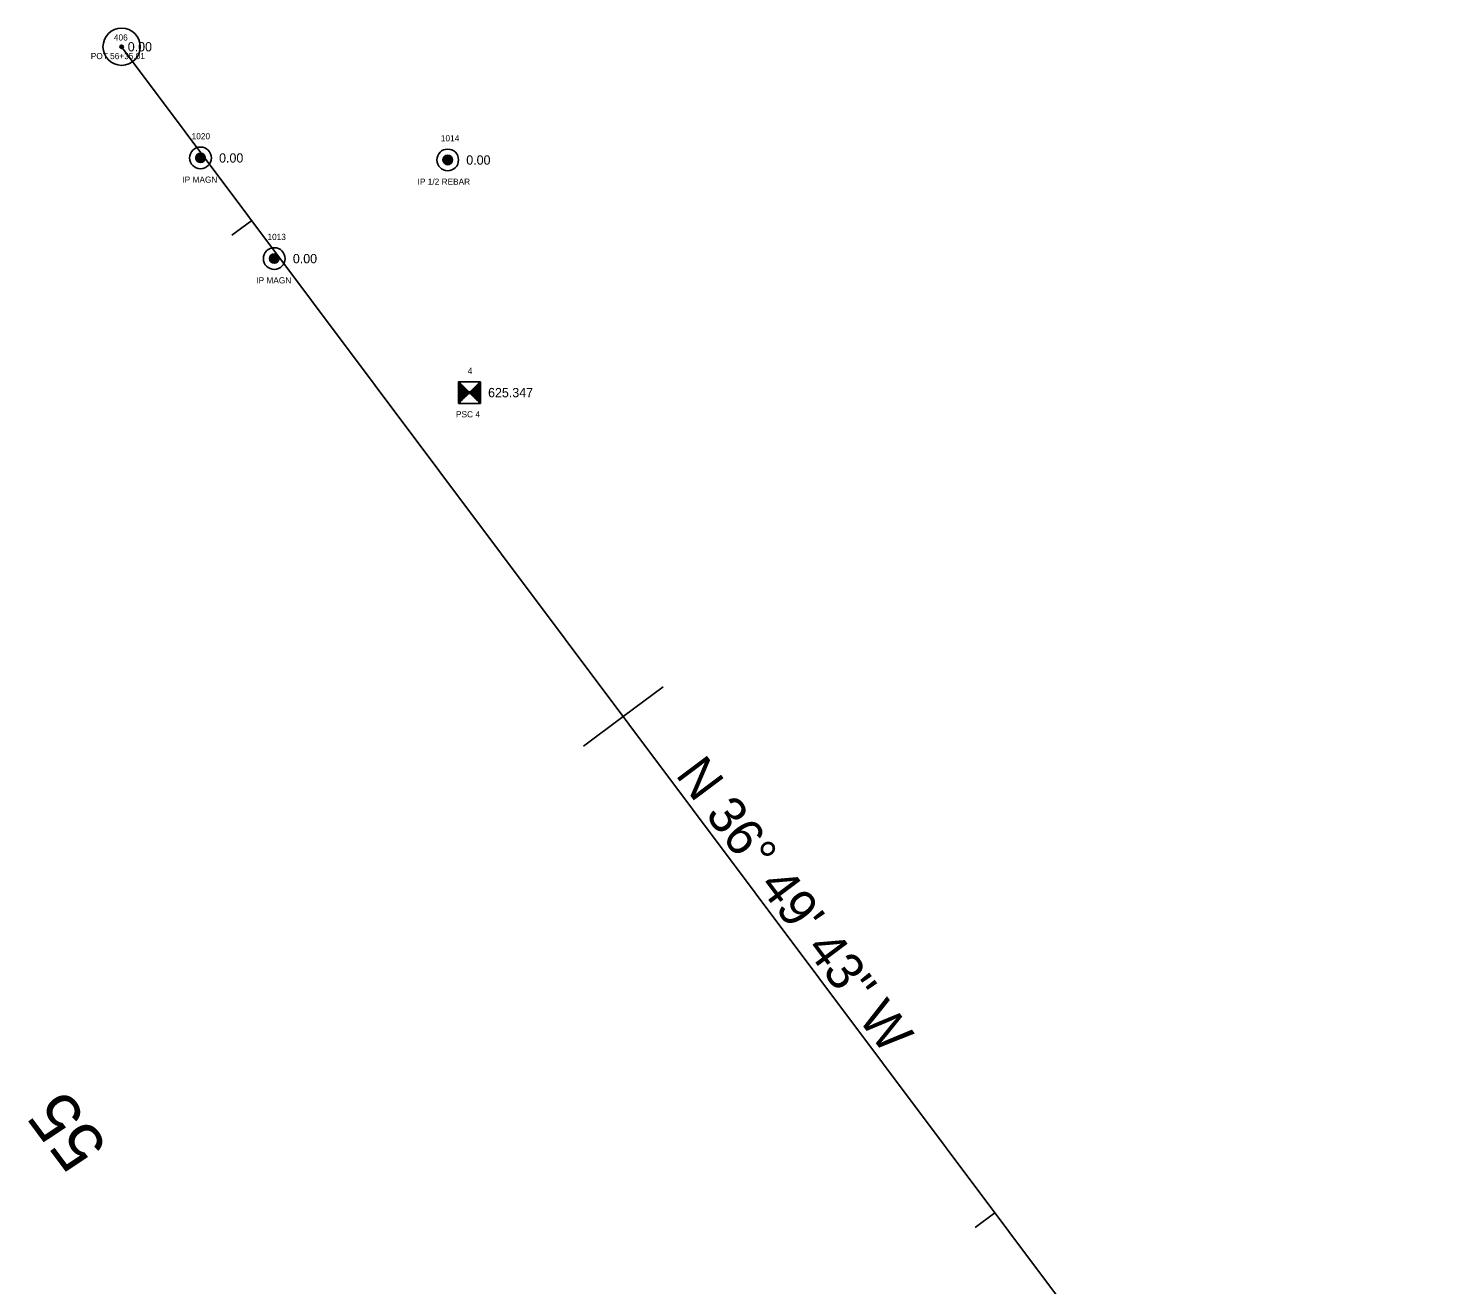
# Model space of a CAD drawing. Extents: x 1538847 to 1546108, y 887169 to 888935.
# Drawn here: x 1539801.6 to 1540028.6, y 887929.8 to 888132.6 of the extents above; entities that cross this region are included whole.
import ezdxf

# ---------------------------------------------------------------- set-up
doc = ezdxf.new("R2010")
doc.units = 0
for name, color, linetype in [('Default', 7, 'Continuous'), ('RD_EX_DV_Prop_txCode', 7, 'Continuous'), ('RD_EX_DV_PropPin', 7, 'Continuous'), ('RD_EX_TX_DV_Prop_ELEV', 7, 'Continuous'), ('RD_HC_Cl', 7, 'Continuous'), ('RD_HC_Data', 7, 'Continuous'), ('RD_HC_Data_Tic', 7, 'Continuous'), ('RD_HC_Survey', 7, 'Continuous'), ('RD_HC_Survey_ELEV', 7, 'Continuous'), ('RD_HC_TX_Sta50', 7, 'Continuous'), ('RD_HC_txCode', 7, 'Continuous'), ('RD_SMD_Locator', 7, 'Continuous')]:
    doc.layers.add(name, color=color, linetype=linetype)

msp = doc.modelspace()

# ---------------------------------------------------------------- linework, layer by layer
at = {"layer": 'Default'}
msp.add_line((1540028.65, 887846.48), (1539816.65, 888129.56), dxfattribs=at)
at = {"layer": 'RD_EX_DV_PropPin'}
for p, q in [((1539828.64, 888111.43), (1539828.64, 888111.82)), ((1539828.68, 888111.32), (1539828.68, 888111.92)), ((1539828.71, 888111.25), (1539828.71, 888111.99)), ((1539828.75, 888111.2), (1539828.75, 888112.05)), ((1539828.78, 888111.15), (1539828.78, 888112.1)), ((1539828.82, 888111.11), (1539828.82, 888112.14)), ((1539828.85, 888111.07), (1539828.85, 888112.17)), ((1539828.89, 888111.04), (1539828.89, 888112.2)), ((1539828.92, 888111.01), (1539828.92, 888112.23)), ((1539828.96, 888110.99), (1539828.96, 888112.26)), ((1539828.99, 888110.97), (1539828.99, 888112.28)), ((1539829.03, 888110.95), (1539829.03, 888112.3)), ((1539829.06, 888110.93), (1539829.06, 888112.32)), ((1539829.1, 888110.92), (1539829.1, 888112.33)), ((1539829.13, 888110.9), (1539829.13, 888112.34)), ((1539829.17, 888110.89), (1539829.17, 888112.35)), ((1539829.2, 888110.88), (1539829.2, 888112.36)), ((1539829.24, 888110.87), (1539829.24, 888112.37)), ((1539829.27, 888110.87), (1539829.27, 888112.38)), ((1539829.31, 888110.86), (1539829.31, 888112.38)), ((1539829.34, 888110.86), (1539829.34, 888112.38)), ((1539829.38, 888110.86), (1539829.38, 888112.38)), ((1539829.41, 888110.86), (1539829.41, 888112.38)), ((1539829.45, 888110.86), (1539829.45, 888112.38)), ((1539829.48, 888110.87), (1539829.48, 888112.38)), ((1539829.52, 888110.87), (1539829.52, 888112.37)), ((1539829.55, 888110.88), (1539829.55, 888112.36)), ((1539829.59, 888110.89), (1539829.59, 888112.35)), ((1539829.62, 888110.9), (1539829.62, 888112.34)), ((1539829.66, 888110.92), (1539829.66, 888112.33)), ((1539829.69, 888110.93), (1539829.69, 888112.32)), ((1539829.73, 888110.95), (1539829.73, 888112.3)), ((1539829.76, 888110.97), (1539829.76, 888112.28)), ((1539829.8, 888110.99), (1539829.8, 888112.26)), ((1539829.83, 888111.01), (1539829.83, 888112.23)), ((1539829.87, 888111.04), (1539829.87, 888112.2)), ((1539829.9, 888111.07), (1539829.9, 888112.17)), ((1539829.94, 888111.11), (1539829.94, 888112.14)), ((1539829.97, 888111.15), (1539829.97, 888112.1)), ((1539830.01, 888111.2), (1539830.01, 888112.05)), ((1539830.04, 888111.25), (1539830.04, 888111.99)), ((1539830.08, 888111.32), (1539830.08, 888111.92)), ((1539830.11, 888111.43), (1539830.11, 888111.82)), ((1539868.52, 888111.09), (1539868.52, 888111.48)), ((1539868.55, 888110.99), (1539868.55, 888111.58)), ((1539868.59, 888110.92), (1539868.59, 888111.66)), ((1539868.62, 888110.86), (1539868.62, 888111.71)), ((1539868.66, 888110.81), (1539868.66, 888111.76)), ((1539868.69, 888110.77), (1539868.69, 888111.8)), ((1539868.73, 888110.74), (1539868.73, 888111.84)), ((1539868.76, 888110.7), (1539868.76, 888111.87)), ((1539868.8, 888110.68), (1539868.8, 888111.9)), ((1539868.83, 888110.65), (1539868.83, 888111.92)), ((1539868.87, 888110.63), (1539868.87, 888111.94)), ((1539868.9, 888110.61), (1539868.9, 888111.96)), ((1539868.94, 888110.59), (1539868.94, 888111.98)), ((1539868.97, 888110.58), (1539868.97, 888111.99)), ((1539869.01, 888110.57), (1539869.01, 888112.01)), ((1539869.04, 888110.55), (1539869.04, 888112.02)), ((1539869.08, 888110.55), (1539869.08, 888112.03)), ((1539869.11, 888110.54), (1539869.11, 888112.03)), ((1539869.15, 888110.53), (1539869.15, 888112.04)), ((1539869.18, 888110.53), (1539869.18, 888112.04)), ((1539869.22, 888110.53), (1539869.22, 888112.05)), ((1539869.25, 888110.52), (1539869.25, 888112.05)), ((1539869.29, 888110.53), (1539869.29, 888112.05)), ((1539869.32, 888110.53), (1539869.32, 888112.04)), ((1539869.36, 888110.53), (1539869.36, 888112.04)), ((1539869.39, 888110.54), (1539869.39, 888112.03)), ((1539869.43, 888110.55), (1539869.43, 888112.03)), ((1539869.46, 888110.55), (1539869.46, 888112.02)), ((1539869.5, 888110.57), (1539869.5, 888112.01)), ((1539869.53, 888110.58), (1539869.53, 888111.99)), ((1539869.57, 888110.59), (1539869.57, 888111.98)), ((1539869.6, 888110.61), (1539869.6, 888111.96)), ((1539869.64, 888110.63), (1539869.64, 888111.94)), ((1539869.67, 888110.65), (1539869.67, 888111.92)), ((1539869.71, 888110.68), (1539869.71, 888111.9)), ((1539869.74, 888110.7), (1539869.74, 888111.87)), ((1539869.78, 888110.74), (1539869.78, 888111.84)), ((1539869.81, 888110.77), (1539869.81, 888111.8)), ((1539869.85, 888110.81), (1539869.85, 888111.76)), ((1539869.88, 888110.86), (1539869.88, 888111.71)), ((1539869.92, 888110.92), (1539869.92, 888111.66)), ((1539869.95, 888110.99), (1539869.95, 888111.58)), ((1539869.99, 888111.09), (1539869.99, 888111.48)), ((1539840.55, 888095.18), (1539840.55, 888095.58)), ((1539840.58, 888095.08), (1539840.58, 888095.68)), ((1539840.62, 888095.01), (1539840.62, 888095.75)), ((1539840.65, 888094.95), (1539840.65, 888095.81)), ((1539840.69, 888094.91), (1539840.69, 888095.85)), ((1539840.72, 888094.87), (1539840.72, 888095.9)), ((1539840.76, 888094.83), (1539840.76, 888095.93)), ((1539840.79, 888094.8), (1539840.79, 888095.96)), ((1539840.83, 888094.77), (1539840.83, 888095.99)), ((1539840.86, 888094.75), (1539840.86, 888096.02)), ((1539840.9, 888094.72), (1539840.9, 888096.04)), ((1539840.93, 888094.7), (1539840.93, 888096.06)), ((1539840.97, 888094.69), (1539840.97, 888096.07)), ((1539841, 888094.67), (1539841, 888096.09)), ((1539841.04, 888094.66), (1539841.04, 888096.1)), ((1539841.07, 888094.65), (1539841.07, 888096.11)), ((1539841.11, 888094.64), (1539841.11, 888096.12)), ((1539841.14, 888094.63), (1539841.14, 888096.13)), ((1539841.18, 888094.63), (1539841.18, 888096.13)), ((1539841.21, 888094.62), (1539841.21, 888096.14)), ((1539841.25, 888094.62), (1539841.25, 888096.14)), ((1539841.28, 888094.62), (1539841.28, 888096.14)), ((1539841.32, 888094.62), (1539841.32, 888096.14)), ((1539841.35, 888094.62), (1539841.35, 888096.14)), ((1539841.39, 888094.63), (1539841.39, 888096.13)), ((1539841.42, 888094.63), (1539841.42, 888096.13)), ((1539841.46, 888094.64), (1539841.46, 888096.12)), ((1539841.49, 888094.65), (1539841.49, 888096.11)), ((1539841.53, 888094.66), (1539841.53, 888096.1)), ((1539841.56, 888094.67), (1539841.56, 888096.09)), ((1539841.6, 888094.69), (1539841.6, 888096.07)), ((1539841.63, 888094.7), (1539841.63, 888096.06)), ((1539841.67, 888094.72), (1539841.67, 888096.04)), ((1539841.7, 888094.75), (1539841.7, 888096.02)), ((1539841.74, 888094.77), (1539841.74, 888095.99)), ((1539841.77, 888094.8), (1539841.77, 888095.96)), ((1539841.81, 888094.83), (1539841.81, 888095.93)), ((1539841.84, 888094.87), (1539841.84, 888095.9)), ((1539841.88, 888094.91), (1539841.88, 888095.85)), ((1539841.91, 888094.95), (1539841.91, 888095.81)), ((1539841.95, 888095.01), (1539841.95, 888095.75)), ((1539841.98, 888095.08), (1539841.98, 888095.68)), ((1539842.02, 888095.18), (1539842.02, 888095.58))]:
    msp.add_line(p, q, dxfattribs=at)
for centre, radius in [((1539829.38, 888111.62), 1.75), ((1539829.38, 888111.62), 0.761), ((1539869.25, 888111.29), 1.75), ((1539869.25, 888111.29), 0.761), ((1539841.28, 888095.38), 1.75), ((1539841.28, 888095.38), 0.761)]:
    msp.add_circle(centre, radius, dxfattribs=at)
at = {"layer": 'RD_HC_Cl'}
msp.add_line((1540028.65, 887846.48), (1539816.65, 888129.56), dxfattribs=at)
at = {"layer": 'RD_HC_Data'}
for radius in [3, 0.282]:
    msp.add_circle((1539816.65, 888129.56), radius, dxfattribs=at)
at = {"layer": 'RD_HC_Data_Tic'}
for p, q in [((1539837.64, 888101.54), (1539834.44, 888099.14)), ((1539897.58, 888021.49), (1539903.99, 888026.29)), ((1539897.58, 888021.49), (1539891.18, 888016.7)), ((1539957.53, 887941.45), (1539954.32, 887939.05))]:
    msp.add_line(p, q, dxfattribs=at)
at = {"layer": 'RD_HC_Survey'}
for p, q in [((1539871.02, 888075.51), (1539874.52, 888072.01)), ((1539874.52, 888075.51), (1539871.02, 888072.01)), ((1539871.04, 888075.48), (1539871.04, 888072.03)), ((1539871.07, 888075.46), (1539871.07, 888072.06)), ((1539871.09, 888075.44), (1539871.09, 888072.08)), ((1539871.12, 888075.41), (1539871.12, 888072.11)), ((1539871.14, 888075.39), (1539871.14, 888072.13)), ((1539871.17, 888075.36), (1539871.17, 888072.16)), ((1539871.19, 888075.34), (1539871.19, 888072.18)), ((1539871.22, 888075.31), (1539871.22, 888072.21)), ((1539871.24, 888075.29), (1539871.24, 888072.23)), ((1539871.27, 888075.26), (1539871.27, 888072.26)), ((1539871.29, 888075.24), (1539871.29, 888072.28)), ((1539871.31, 888075.21), (1539871.31, 888072.31)), ((1539871.34, 888075.19), (1539871.34, 888072.33)), ((1539871.36, 888075.16), (1539871.36, 888072.36)), ((1539871.39, 888075.14), (1539871.39, 888072.38)), ((1539871.41, 888075.11), (1539871.41, 888072.41)), ((1539871.44, 888075.09), (1539871.44, 888072.43)), ((1539871.46, 888075.06), (1539871.46, 888072.45)), ((1539871.49, 888075.04), (1539871.49, 888072.48)), ((1539871.51, 888075.01), (1539871.51, 888072.5)), ((1539871.54, 888074.99), (1539871.54, 888072.53)), ((1539871.56, 888074.97), (1539871.56, 888072.55)), ((1539871.59, 888074.94), (1539871.59, 888072.58)), ((1539871.61, 888074.92), (1539871.61, 888072.6)), ((1539871.64, 888074.89), (1539871.64, 888072.63)), ((1539871.66, 888074.87), (1539871.66, 888072.65)), ((1539871.69, 888074.84), (1539871.69, 888072.68)), ((1539871.71, 888074.82), (1539871.71, 888072.7)), ((1539871.74, 888074.79), (1539871.74, 888072.73)), ((1539871.76, 888074.77), (1539871.76, 888072.75)), ((1539871.79, 888074.74), (1539871.79, 888072.78)), ((1539871.81, 888074.72), (1539871.81, 888072.8)), ((1539873.73, 888074.72), (1539873.73, 888072.8)), ((1539873.75, 888074.74), (1539873.75, 888072.78)), ((1539873.78, 888074.77), (1539873.78, 888072.75)), ((1539873.8, 888074.79), (1539873.8, 888072.73)), ((1539873.82, 888074.82), (1539873.82, 888072.7)), ((1539873.85, 888074.84), (1539873.85, 888072.68)), ((1539873.87, 888074.87), (1539873.87, 888072.65)), ((1539873.9, 888074.89), (1539873.9, 888072.63)), ((1539873.92, 888074.92), (1539873.92, 888072.6)), ((1539873.95, 888074.94), (1539873.95, 888072.58)), ((1539873.97, 888074.97), (1539873.97, 888072.55)), ((1539874, 888074.99), (1539874, 888072.53)), ((1539874.02, 888075.01), (1539874.02, 888072.5)), ((1539874.05, 888075.04), (1539874.05, 888072.48)), ((1539874.07, 888075.06), (1539874.07, 888072.45)), ((1539874.1, 888075.09), (1539874.1, 888072.43)), ((1539874.12, 888075.11), (1539874.12, 888072.41)), ((1539874.15, 888075.14), (1539874.15, 888072.38)), ((1539874.17, 888075.16), (1539874.17, 888072.36)), ((1539874.2, 888075.19), (1539874.2, 888072.33)), ((1539874.22, 888075.21), (1539874.22, 888072.31)), ((1539874.25, 888075.24), (1539874.25, 888072.28)), ((1539874.27, 888075.26), (1539874.27, 888072.26)), ((1539874.3, 888075.29), (1539874.3, 888072.23)), ((1539874.32, 888075.31), (1539874.32, 888072.21)), ((1539874.34, 888075.34), (1539874.34, 888072.18)), ((1539874.37, 888075.36), (1539874.37, 888072.16)), ((1539874.39, 888075.39), (1539874.39, 888072.13)), ((1539874.42, 888075.41), (1539874.42, 888072.11)), ((1539874.44, 888075.44), (1539874.44, 888072.08)), ((1539874.47, 888075.46), (1539874.47, 888072.06)), ((1539874.49, 888075.48), (1539874.49, 888072.03)), ((1539871.83, 888074.69), (1539871.83, 888072.83)), ((1539871.86, 888074.67), (1539871.86, 888072.85)), ((1539871.88, 888074.64), (1539871.88, 888072.88)), ((1539871.91, 888074.62), (1539871.91, 888072.9)), ((1539871.93, 888074.59), (1539871.93, 888072.93)), ((1539871.96, 888074.57), (1539871.96, 888072.95)), ((1539871.98, 888074.54), (1539871.98, 888072.97)), ((1539872.01, 888074.52), (1539872.01, 888073)), ((1539872.03, 888074.49), (1539872.03, 888073.02)), ((1539872.06, 888074.47), (1539872.06, 888073.05)), ((1539872.08, 888074.45), (1539872.08, 888073.07)), ((1539872.11, 888074.42), (1539872.11, 888073.1)), ((1539872.13, 888074.4), (1539872.13, 888073.12)), ((1539872.16, 888074.37), (1539872.16, 888073.15)), ((1539872.18, 888074.35), (1539872.18, 888073.17)), ((1539872.21, 888074.32), (1539872.21, 888073.2)), ((1539872.23, 888074.3), (1539872.23, 888073.22)), ((1539872.26, 888074.27), (1539872.26, 888073.25)), ((1539872.28, 888074.25), (1539872.28, 888073.27)), ((1539872.3, 888074.22), (1539872.3, 888073.3)), ((1539872.33, 888074.2), (1539872.33, 888073.32)), ((1539872.35, 888074.17), (1539872.35, 888073.35)), ((1539872.38, 888074.15), (1539872.38, 888073.37)), ((1539872.4, 888074.12), (1539872.4, 888073.4)), ((1539872.43, 888074.1), (1539872.43, 888073.42)), ((1539872.45, 888074.07), (1539872.45, 888073.44)), ((1539872.48, 888074.05), (1539872.48, 888073.47)), ((1539872.5, 888074.02), (1539872.5, 888073.49)), ((1539872.53, 888074), (1539872.53, 888073.52)), ((1539872.55, 888073.98), (1539872.55, 888073.54)), ((1539872.58, 888073.95), (1539872.58, 888073.57)), ((1539872.6, 888073.93), (1539872.6, 888073.59)), ((1539872.63, 888073.9), (1539872.63, 888073.62)), ((1539872.65, 888073.88), (1539872.65, 888073.64)), ((1539872.68, 888073.85), (1539872.68, 888073.67)), ((1539872.7, 888073.83), (1539872.7, 888073.69)), ((1539872.73, 888073.8), (1539872.73, 888073.72)), ((1539872.75, 888073.78), (1539872.75, 888073.74)), ((1539872.79, 888073.78), (1539872.79, 888073.74)), ((1539872.81, 888073.8), (1539872.81, 888073.72)), ((1539872.83, 888073.83), (1539872.83, 888073.69)), ((1539872.86, 888073.85), (1539872.86, 888073.67)), ((1539872.88, 888073.88), (1539872.88, 888073.64)), ((1539872.91, 888073.9), (1539872.91, 888073.62)), ((1539872.93, 888073.93), (1539872.93, 888073.59)), ((1539872.96, 888073.95), (1539872.96, 888073.57)), ((1539872.98, 888073.98), (1539872.98, 888073.54)), ((1539873.01, 888074), (1539873.01, 888073.52)), ((1539873.03, 888074.02), (1539873.03, 888073.49)), ((1539873.06, 888074.05), (1539873.06, 888073.47)), ((1539873.08, 888074.07), (1539873.08, 888073.44)), ((1539873.11, 888074.1), (1539873.11, 888073.42)), ((1539873.13, 888074.12), (1539873.13, 888073.4)), ((1539873.16, 888074.15), (1539873.16, 888073.37)), ((1539873.18, 888074.17), (1539873.18, 888073.35)), ((1539873.21, 888074.2), (1539873.21, 888073.32)), ((1539873.23, 888074.22), (1539873.23, 888073.3)), ((1539873.26, 888074.25), (1539873.26, 888073.27)), ((1539873.28, 888074.27), (1539873.28, 888073.25)), ((1539873.31, 888074.3), (1539873.31, 888073.22)), ((1539873.33, 888074.32), (1539873.33, 888073.2)), ((1539873.35, 888074.35), (1539873.35, 888073.17)), ((1539873.38, 888074.37), (1539873.38, 888073.15)), ((1539873.4, 888074.4), (1539873.4, 888073.12)), ((1539873.43, 888074.42), (1539873.43, 888073.1)), ((1539873.45, 888074.45), (1539873.45, 888073.07)), ((1539873.48, 888074.47), (1539873.48, 888073.05)), ((1539873.5, 888074.49), (1539873.5, 888073.02)), ((1539873.53, 888074.52), (1539873.53, 888073)), ((1539873.55, 888074.54), (1539873.55, 888072.97)), ((1539873.58, 888074.57), (1539873.58, 888072.95)), ((1539873.6, 888074.59), (1539873.6, 888072.93)), ((1539873.63, 888074.62), (1539873.63, 888072.9)), ((1539873.65, 888074.64), (1539873.65, 888072.88)), ((1539873.68, 888074.67), (1539873.68, 888072.85)), ((1539873.7, 888074.69), (1539873.7, 888072.83))]:
    msp.add_line(p, q, dxfattribs=at)
msp.add_lwpolyline([(1539874.52, 888075.51), (1539871.02, 888075.51), (1539871.02, 888072.01), (1539874.52, 888072.01)], close=True, dxfattribs=at)
at = {"layer": 'RD_SMD_Locator'}
for centre in [(1539816.65, 888129.56), (1539829.38, 888111.62), (1539869.25, 888111.29), (1539841.28, 888095.38), (1539872.77, 888073.76)]:
    msp.add_circle(centre, 0.15, dxfattribs=at)

# ---------------------------------------------------------------- texts
at = {"layer": 'RD_EX_DV_Prop_txCode'}
for s, p in [('1020', (1539827.95, 888114.62)), ('1014', (1539868.15, 888114.29)), ('IP MAGN', (1539826.46, 888107.62)), ('IP 1/2 REBAR', (1539864.4, 888107.29)), ('1013', (1539840.18, 888098.38)), ('IP MAGN', (1539838.37, 888091.38))]:
    msp.add_text(s, height=1, dxfattribs=at).set_placement(p)
at = {"layer": 'RD_EX_TX_DV_Prop_ELEV'}
for p in [(1539832.38, 888110.87), (1539872.25, 888110.54), (1539844.28, 888094.63)]:
    msp.add_text('0.00', height=1.5, dxfattribs=at).set_placement(p)
at = {"layer": 'RD_HC_Data'}
msp.add_text('N 36%%d 49\' 43" W', height=6, rotation=306.8285, dxfattribs=at).set_placement((1539905.87, 888012.09))
at = {"layer": 'RD_HC_Survey_ELEV'}
for s, p in [('0.00', (1539817.65, 888128.81)), ('625.347', (1539875.77, 888073.01))]:
    msp.add_text(s, height=1.5, dxfattribs=at).set_placement(p)
at = {"layer": 'RD_HC_TX_Sta50'}
msp.add_text('55', height=8, rotation=126.8285, dxfattribs=at).set_placement((1539814.59, 887952.14))
at = {"layer": 'RD_HC_txCode'}
for s, p in [('406', (1539815.41, 888130.56)), ('POT 56+35.01', (1539811.68, 888127.56)), ('4', (1539872.48, 888076.76)), ('PSC 4', (1539870.59, 888069.76))]:
    msp.add_text(s, height=1, dxfattribs=at).set_placement(p)

doc.saveas('drawing.dxf')
